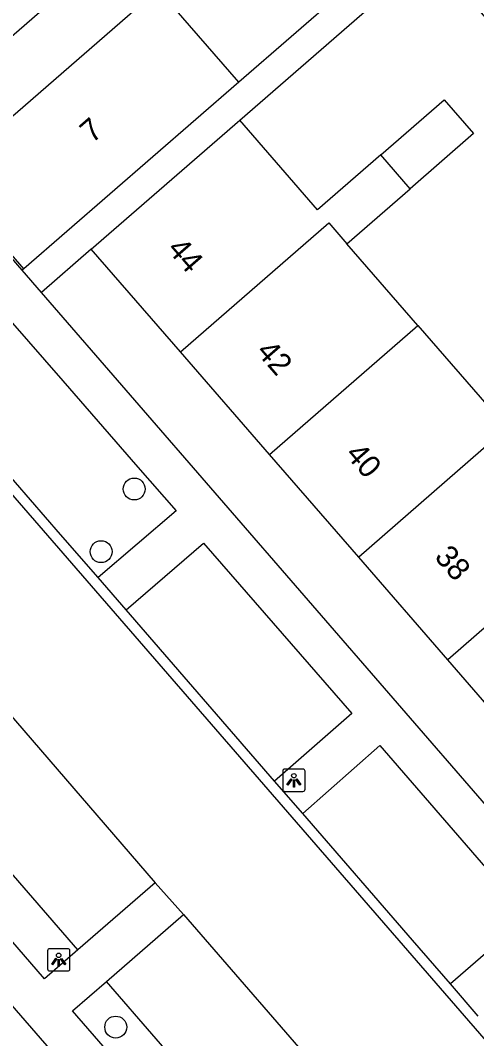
# Model space of a CAD drawing. Extents: x 155888 to 156864, y 383882 to 384671.
# Drawn here: x 156592.97 to 156613.37, y 384066.28 to 384111.77 of the extents above; entities that cross this region are included whole.
import ezdxf

# ---------------------------------------------------------------- set-up
doc = ezdxf.new("R2010")
doc.units = 0
for name, color, linetype in [('IMGEO_Boom', 7, 'Continuous'), ('IMGEO_Lichtpunt', 7, 'Continuous'), ('IMGEO_Pand', 7, 'Continuous'), ('IMGEO_Pand_nummerreeks', 7, 'Continuous'), ('IMGEO_Parkeervlak_open', 7, 'Continuous'), ('IMGEO_Rijbaan_lokaal_gesloten', 7, 'Continuous'), ('IMGEO_Rijbaan_lokaal_open', 7, 'Continuous'), ('IMGEO_Voetpad_open', 7, 'Continuous')]:
    doc.layers.add(name, color=color, linetype=linetype)

msp = doc.modelspace()

# ---------------------------------------------------------------- linework, layer by layer
at = {"layer": 'IMGEO_Boom'}
for centre in [(156598.061, 384090.837), (156596.58, 384088.039), (156597.234, 384066.801)]:
    msp.add_circle(centre, 0.489, dxfattribs=at)
at = {"layer": 'IMGEO_Lichtpunt'}
for p, q in [((156605.601, 384078.325), (156604.793, 384078.325)), ((156605.601, 384078.325), (156604.793, 384078.325)), ((156604.699, 384078.23), (156604.699, 384077.423)), ((156604.699, 384078.23), (156604.699, 384077.423)), ((156605.695, 384077.423), (156605.695, 384078.23)), ((156605.695, 384077.423), (156605.695, 384078.23)), ((156604.793, 384077.329), (156605.601, 384077.329)), ((156604.793, 384077.329), (156605.601, 384077.329)), ((156594.186, 384070.208), (156594.186, 384069.401)), ((156594.186, 384070.208), (156594.186, 384069.401)), ((156595.088, 384070.303), (156594.28, 384070.303)), ((156595.088, 384070.303), (156594.28, 384070.303)), ((156595.182, 384069.401), (156595.182, 384070.208)), ((156595.182, 384069.401), (156595.182, 384070.208)), ((156594.28, 384069.307), (156595.088, 384069.307)), ((156594.28, 384069.307), (156595.088, 384069.307))]:
    msp.add_line(p, q, dxfattribs=at)
for points in [[(156605.073, 384077.894), (156605.112, 384077.866), (156604.924, 384077.604), (156604.886, 384077.631), (156605.073, 384077.894)], [(156605.175, 384077.846), (156605.222, 384077.846), (156605.222, 384077.524), (156605.175, 384077.524), (156605.175, 384077.846)], [(156605.285, 384077.866), (156605.323, 384077.893), (156605.51, 384077.631), (156605.471, 384077.603), (156605.285, 384077.866)], [(156594.56, 384069.872), (156594.599, 384069.844), (156594.411, 384069.582), (156594.373, 384069.609), (156594.56, 384069.872)], [(156594.662, 384069.824), (156594.709, 384069.824), (156594.709, 384069.502), (156594.662, 384069.502), (156594.662, 384069.824)], [(156594.772, 384069.844), (156594.81, 384069.871), (156594.997, 384069.609), (156594.958, 384069.581), (156594.772, 384069.844)]]:
    msp.add_lwpolyline(points, dxfattribs=at)
for centre in [(156605.198, 384078.028), (156594.685, 384070.006)]:
    msp.add_circle(centre, 0.0994, dxfattribs=at)
for centre, start, end in [((156604.793, 384078.23), 90, 180), ((156604.793, 384078.23), 90, 180), ((156605.601, 384078.23), 0, 90), ((156605.601, 384078.23), 0, 90), ((156604.793, 384077.423), 180, 270), ((156604.793, 384077.423), 180, 270), ((156605.601, 384077.423), 270, 0), ((156605.601, 384077.423), 270, 360), ((156594.28, 384070.208), 90, 180), ((156594.28, 384070.208), 90, 180), ((156595.088, 384070.208), 0, 90), ((156595.088, 384070.208), 0, 90), ((156594.28, 384069.401), 180, 270), ((156594.28, 384069.401), 180, 270), ((156595.088, 384069.401), 270, 0), ((156595.088, 384069.401), 270, 360)]:
    msp.add_arc(centre, 0.0946, start, end, dxfattribs=at)
at = {"layer": 'IMGEO_Pand'}
for points in [[(156612.102, 384117.132), (156602.741, 384109.01)], [(156593.133, 384100.673), (156589.53, 384104.822), (156599.132, 384113.164)], [(156602.741, 384109.01), (156599.132, 384113.164)], [(156602.741, 384109.01), (156593.133, 384100.673)], [(156609.091, 384105.765), (156611.922, 384108.224), (156613.234, 384106.714), (156610.403, 384104.255)], [(156596.143, 384101.55), (156602.78, 384107.311)], [(156609.091, 384105.765), (156606.26, 384103.305), (156602.78, 384107.311)], [(156610.403, 384104.255), (156609.091, 384105.765)], [(156607.572, 384101.795), (156610.403, 384104.255)], [(156600.131, 384096.96), (156606.761, 384102.729), (156607.572, 384101.795)], [(156600.131, 384096.96), (156596.143, 384101.55)], [(156610.742, 384098.146), (156607.572, 384101.795)], [(156604.113, 384092.376), (156610.742, 384098.146)], [(156610.742, 384098.146), (156614.127, 384094.249), (156616.958, 384096.709)], [(156604.113, 384092.376), (156600.131, 384096.96)], [(156615.439, 384092.739), (156614.724, 384093.562), (156608.096, 384087.792)], [(156608.096, 384087.792), (156604.113, 384092.376)], [(156618.706, 384088.978), (156612.078, 384083.208)], [(156612.078, 384083.208), (156608.096, 384087.792)], [(156616.061, 384078.623), (156612.078, 384083.208)]]:
    msp.add_lwpolyline(points, dxfattribs=at)
at = {"layer": 'IMGEO_Parkeervlak_open'}
for points in [[(156595.54, 384070.25), (156588.905, 384077.888)], [(156603.477, 384061.151), (156596.818, 384068.832)]]:
    msp.add_lwpolyline(points, dxfattribs=at)
at = {"layer": 'IMGEO_Rijbaan_lokaal_gesloten'}
for points in [[(156584.127, 384100.331), (156646.454, 384028.54), (156658.614, 384014.564)], [(156592.38, 384080.913), (156599, 384073.239)], [(156599, 384073.239), (156600.266, 384071.831)], [(156600.266, 384071.831), (156606.948, 384064.118)]]:
    msp.add_lwpolyline(points, dxfattribs=at)
at = {"layer": 'IMGEO_Rijbaan_lokaal_open'}
for points in [[(156596.453, 384086.892), (156594.77, 384088.811), (156591.404, 384092.681), (156590.413, 384093.818), (156589.043, 384095.382)], [(156597.706, 384085.44), (156596.453, 384086.892)], [(156604.336, 384077.785), (156597.706, 384085.44)], [(156605.598, 384076.349), (156604.336, 384077.785)], [(156612.193, 384068.739), (156610.506, 384070.683), (156605.598, 384076.349)], [(156613.441, 384067.288), (156612.193, 384068.739)]]:
    msp.add_lwpolyline(points, dxfattribs=at)
at = {"layer": 'IMGEO_Voetpad_open'}
for points in [[(156587.667, 384106.816), (156626.242, 384140.297)], [(156602.78, 384107.311), (156611.304, 384114.726), (156643.166, 384078.047)], [(156593.045, 384100.611), (156589.344, 384104.881), (156587.667, 384106.816)], [(156596.143, 384101.55), (156593.911, 384099.613)], [(156593.133, 384100.673), (156593.045, 384100.611)], [(156593.911, 384099.613), (156593.045, 384100.611)], [(156625.75, 384062.919), (156593.911, 384099.613)], [(156589.043, 384095.382), (156590.839, 384096.907), (156592.517, 384098.365), (156594.87, 384095.667), (156598.216, 384091.811), (156599.93, 384089.87), (156596.453, 384086.892)], [(156597.706, 384085.44), (156601.151, 384088.422), (156607.783, 384080.814), (156604.336, 384077.785)], [(156577.371, 384085.262), (156609.255, 384048.581)], [(156605.598, 384076.349), (156609.04, 384079.373), (156613.955, 384073.708), (156615.658, 384071.729), (156612.193, 384068.739)], [(156595.54, 384070.25), (156594.055, 384068.957), (156587.433, 384076.599), (156588.905, 384077.888)], [(156599, 384073.239), (156595.54, 384070.25)], [(156596.818, 384068.832), (156600.266, 384071.831)], [(156603.477, 384061.151), (156601.979, 384059.84), (156595.295, 384067.53), (156596.818, 384068.832)]]:
    msp.add_lwpolyline(points, dxfattribs=at)

# ---------------------------------------------------------------- texts
at = {"layer": 'IMGEO_Pand_nummerreeks'}
for s, rotation, p in [('7', 40.9816, (156596.181, 384106.255)), ('44', 310.9835, (156599.495, 384101.534)), ('42', 310.9835, (156603.476, 384096.952)), ('40', 310.9835, (156607.462, 384092.364)), ('38', 310.9835, (156611.444, 384087.78))]:
    msp.add_text(s, height=1, rotation=rotation, dxfattribs=at).set_placement(p)

doc.saveas('drawing.dxf')
